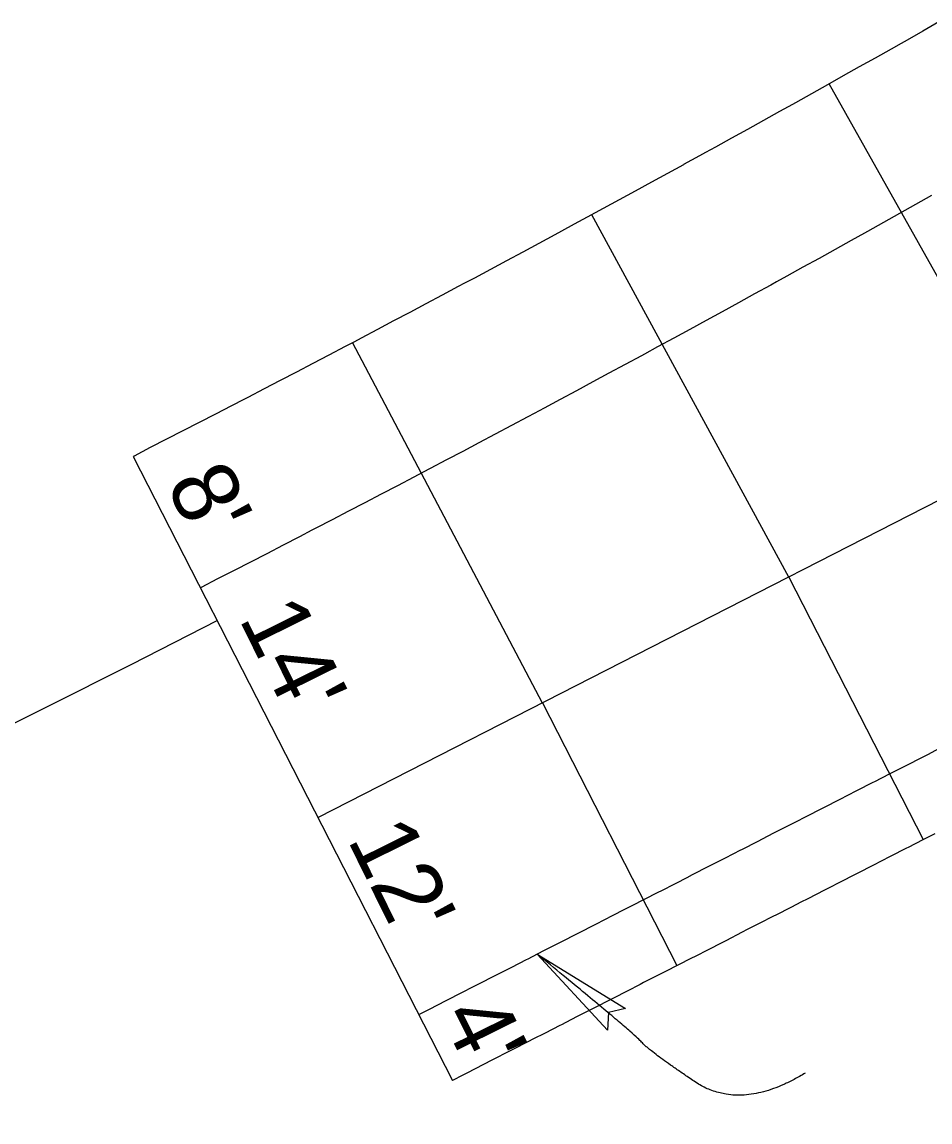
# Model space of a CAD drawing. Extents: x 2145147 to 2158018, y 137519 to 148068.
# Drawn here: x 2149640.5 to 2149689.7, y 143162.9 to 143222.5 of the extents above; entities that cross this region are included whole.
import ezdxf

# ---------------------------------------------------------------- set-up
doc = ezdxf.new("R2010")
doc.units = 0
for name, color, linetype in [('PR_Align_Ramp_A', 7, 'Continuous'), ('PR_Dimensions', 7, 'Continuous'), ('PR_Joint_Contraction', 7, 'Continuous'), ('PR_Joint_Long', 7, 'Continuous'), ('PR_Road_Concrete', 7, 'Continuous')]:
    doc.layers.add(name, color=color, linetype=linetype)

msp = doc.modelspace()

# ---------------------------------------------------------------- linework, layer by layer
at = {"layer": 'PR_Align_Ramp_A'}
msp.add_arc((2149129.131, 144210.23), 1145.916, 264.044287, 297.094926, dxfattribs=at)
at = {"layer": 'PR_Dimensions'}
msp.add_lwpolyline([(2149668.394, 143171.987), (2149673.176, 143169.046), (2149672.255, 143168.832), (2149672.199, 143167.865)], close=True, dxfattribs=at)
msp.add_open_spline([(2149682.909, 143165.536), (2149679.412, 143163.402), (2149674.437, 143166.757), (2149673.684, 143167.665), (2149668.394, 143171.987)], degree=2, dxfattribs=at)
at = {"layer": 'PR_Joint_Contraction'}
for p, q in [((2149695.377, 143199.263), (2149684.221, 143219.181)), ((2149682.024, 143192.434), (2149671.351, 143212.081)), ((2149668.674, 143185.607), (2149658.385, 143205.146)), ((2149682.032, 143192.438), (2149689.317, 143178.199)), ((2149668.677, 143185.608), (2149675.963, 143171.367))]:
    msp.add_line(p, q, dxfattribs=at)
at = {"layer": 'PR_Joint_Long'}
msp.add_line((2149708.741, 143206.098), (2149656.522, 143179.392), dxfattribs=at)
for points in [[(2149689.767, 143213.12), (2149688.897, 143212.631), (2149688.026, 143212.143), (2149687.155, 143211.656), (2149686.283, 143211.169), (2149686.122, 143211.079), (2149685.411, 143210.683), (2149684.539, 143210.198), (2149683.666, 143209.714), (2149682.793, 143209.23), (2149681.919, 143208.747), (2149681.367, 143208.443), (2149681.045, 143208.266), (2149680.174, 143207.786), (2149680.17, 143207.784), (2149679.295, 143207.304), (2149678.42, 143206.824), (2149677.544, 143206.345), (2149676.668, 143205.867), (2149675.791, 143205.389), (2149674.914, 143204.913), (2149674.206, 143204.529), (2149674.037, 143204.437), (2149673.158, 143203.962), (2149672.28, 143203.487), (2149671.401, 143203.014), (2149670.522, 143202.541), (2149669.642, 143202.069), (2149668.762, 143201.597), (2149668.22, 143201.307), (2149667.882, 143201.127), (2149667.001, 143200.657), (2149666.12, 143200.188), (2149665.238, 143199.72), (2149664.356, 143199.252), (2149663.474, 143198.786), (2149662.591, 143198.32), (2149662.214, 143198.121), (2149661.708, 143197.855), (2149660.824, 143197.39), (2149659.94, 143196.927), (2149659.056, 143196.464), (2149658.171, 143196.002), (2149657.285, 143195.541), (2149656.399, 143195.08), (2149656.189, 143194.971), (2149655.514, 143194.62), (2149654.627, 143194.161), (2149653.74, 143193.703), (2149652.853, 143193.246), (2149651.965, 143192.789), (2149651.077, 143192.333), (2149650.188, 143191.878), (2149650.146, 143191.856)], [(2149690.143, 143183.114), (2149689.571, 143182.821), (2149689.253, 143182.659), (2149688.362, 143182.203), (2149688.119, 143182.078), (2149687.472, 143181.748), (2149686.667, 143181.336), (2149686.582, 143181.292), (2149685.692, 143180.837), (2149685.215, 143180.593), (2149684.801, 143180.381), (2149683.911, 143179.926), (2149683.764, 143179.85), (2149683.021, 143179.47), (2149682.312, 143179.108), (2149682.131, 143179.015), (2149681.24, 143178.559), (2149680.86, 143178.365), (2149680.35, 143178.104), (2149679.46, 143177.648), (2149679.409, 143177.622), (2149678.57, 143177.193), (2149677.957, 143176.879), (2149677.679, 143176.738), (2149676.789, 143176.282), (2149676.505, 143176.137), (2149675.899, 143175.827), (2149675.053, 143175.394), (2149675.009, 143175.371), (2149674.118, 143174.916), (2149673.602, 143174.651), (2149673.228, 143174.46), (2149672.338, 143174.005), (2149672.15, 143173.909), (2149671.448, 143173.549), (2149670.698, 143173.166), (2149670.557, 143173.094), (2149669.667, 143172.638), (2149669.246, 143172.423), (2149668.777, 143172.183), (2149668.394, 143171.987), (2149667.887, 143171.727), (2149667.795, 143171.68), (2149666.996, 143171.272), (2149666.343, 143170.938), (2149666.106, 143170.816), (2149665.216, 143170.361), (2149664.891, 143170.195), (2149664.326, 143169.906), (2149663.439, 143169.452), (2149663.435, 143169.45), (2149662.545, 143168.995), (2149661.988, 143168.709)]]:
    msp.add_lwpolyline(points, dxfattribs=at)
at = {"layer": 'PR_Road_Concrete'}
msp.add_line((2149646.502, 143198.978), (2149663.81, 143165.148), dxfattribs=at)
for points in [[(2149690.162, 143222.532), (2149689.299, 143222.042), (2149688.437, 143221.554), (2149688.114, 143221.371), (2149687.574, 143221.066), (2149686.71, 143220.579), (2149685.847, 143220.093), (2149684.982, 143219.608), (2149684.118, 143219.123), (2149683.252, 143218.639), (2149682.387, 143218.156), (2149682.227, 143218.067), (2149681.521, 143217.673), (2149680.655, 143217.192), (2149679.788, 143216.711), (2149678.921, 143216.231), (2149678.053, 143215.751), (2149677.505, 143215.449), (2149677.185, 143215.273), (2149676.32, 143214.797), (2149676.316, 143214.795), (2149675.448, 143214.318), (2149674.578, 143213.841), (2149673.708, 143213.366), (2149672.838, 143212.891), (2149671.968, 143212.417), (2149671.097, 143211.943), (2149670.394, 143211.562), (2149670.225, 143211.471), (2149669.354, 143210.999), (2149668.481, 143210.528), (2149667.609, 143210.058), (2149666.736, 143209.588), (2149665.862, 143209.119), (2149664.989, 143208.651), (2149664.449, 143208.363), (2149664.114, 143208.184), (2149663.24, 143207.718), (2149662.365, 143207.252), (2149661.489, 143206.787), (2149660.613, 143206.323), (2149659.737, 143205.859), (2149658.86, 143205.397), (2149658.486, 143205.199), (2149657.983, 143204.935), (2149657.106, 143204.474), (2149656.228, 143204.013), (2149655.35, 143203.554), (2149654.471, 143203.095), (2149653.592, 143202.637), (2149652.712, 143202.18), (2149652.503, 143202.071), (2149651.832, 143201.723), (2149650.952, 143201.267), (2149650.071, 143200.812), (2149649.19, 143200.358), (2149648.309, 143199.905), (2149647.427, 143199.452), (2149646.545, 143199), (2149646.502, 143198.978)], [(2149689.941, 143178.517), (2149689.294, 143178.187), (2149688.489, 143177.775), (2149688.404, 143177.731), (2149687.514, 143177.276), (2149687.037, 143177.032), (2149686.623, 143176.82), (2149685.733, 143176.365), (2149685.586, 143176.289), (2149684.843, 143175.909), (2149684.134, 143175.547), (2149683.953, 143175.454), (2149683.062, 143174.998), (2149682.682, 143174.804), (2149682.172, 143174.543), (2149681.282, 143174.087), (2149681.23, 143174.061), (2149680.392, 143173.632), (2149679.779, 143173.318), (2149679.501, 143173.177), (2149678.611, 143172.721), (2149678.327, 143172.576), (2149677.721, 143172.266), (2149676.875, 143171.833), (2149676.831, 143171.81), (2149675.94, 143171.355), (2149675.423, 143171.09), (2149675.05, 143170.899), (2149674.16, 143170.444), (2149673.972, 143170.348), (2149673.27, 143169.988), (2149672.52, 143169.605), (2149672.379, 143169.533), (2149671.489, 143169.077), (2149671.068, 143168.862), (2149670.599, 143168.622), (2149670.216, 143168.426), (2149669.709, 143168.166), (2149669.617, 143168.119), (2149668.818, 143167.711), (2149668.165, 143167.377), (2149667.928, 143167.255), (2149667.038, 143166.8), (2149666.713, 143166.634), (2149666.148, 143166.345), (2149665.261, 143165.891), (2149665.257, 143165.889), (2149664.367, 143165.434), (2149663.81, 143165.148)]]:
    msp.add_lwpolyline(points, dxfattribs=at)

# ---------------------------------------------------------------- texts
at = {"layer": 'PR_Dimensions'}
for s, p in [("8'", (2149648.243, 143197.458)), ("14'", (2149652.201, 143190.198)), ("12'", (2149658.077, 143178.218)), ("4'", (2149663.131, 143168.635))]:
    msp.add_text(s, height=3.6, rotation=296.33136, dxfattribs=at).set_placement(p)

doc.saveas('drawing.dxf')
